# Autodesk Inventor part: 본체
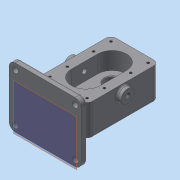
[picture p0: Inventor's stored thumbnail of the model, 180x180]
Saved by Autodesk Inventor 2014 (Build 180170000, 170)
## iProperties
Created: 2026-10
Part Number: 본체
Material: 일반
Document SubType Name: Modeling
Designer: dg
Density: 1 g/cm^3
Appearance: 기본값
Author: dg
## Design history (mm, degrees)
sketch "스케치1"
  geometry: L1 (-40, 60)-(40, 60); L2 (40, 60)-(40, -60); L3 (40, -60)-(-40, -60); L4 (-40, -60)-(-40, 60); 3 further points
  constraints: 8 end point, 2 midpoint, 2 parallel, 1 horizontal, 1 horizontal alignment, 1 perpendicular, 1 vertical alignment
  dimensions: "d0" = 80 distance of L1.start L1.end; "d1" = 120 distance of L3.end L1.start
extrude "돌출1" new body sketch "스케치1" stored distance "d2" = 53; taper "d3" = 0 deg
sketch "스케치2"
  geometry: L1 (-40, 60)-(-40, -60) reference; L2 (0, 22)-(0, -22); L3 (-24, 22)-(-24, -22); L4 (24, -22)-(24, 22); A1 r 24 centre (0, 22) between (24, 22) and (-24, 22); A2 r 24 centre (0, -22) between (-24, -22) and (24, -22); 2 further points
  constraints: 8 end point, 4 point on circle, 4 tangent, 2 centre point, 2 coincident, 2 parallel, 1 midpoint
  dimensions: "d4" = 44 distance of L2.end L2.start; "d6" = 48 distance between parallel lines of L4 L3
extrude "돌출2" cut sketch "스케치2" distance "d7" = 29; taper "d8" = 0 deg
fillet "모깎기1" dims "d9" = 9
sketch "스케치5"
  geometry: C1 r 19 at (0, 22); 1 further point
  constraints: 1 centre point, 1 vertical alignment
  dimensions: "d13" = 22 distance of point (0, 0) C1.centre; "d14" = 38 diameter of C1
extrude "돌출3" join sketch "스케치5" distance "d15" = 17; taper "d16" = 0 deg
sketch "스케치6"
  geometry: L1 (22, -2.623)-(22, -43.5); L2 (3, -43.5)-(41, -43.5) reference; L3 (22, -2.5)-(46, -2.5) reference; L4 (34.5, -2.5)-(34.5, -17.5); L5 (34.5, -17.5)-(30.5, -17.5); L6 (30.5, -17.5)-(30.5, -36.2); L7 (30.5, -36.2)-(36, -36.2); L8 (36, -36.2)-(36, -42.8); L9 (36, -42.8)-(36.404, -43.5); L10 (-22, -2.623)-(-22, -17.5); L11 (-22, -17.5)-(-9.5, -17.5); L12 (-9.5, -17.5)-(-9.5, -2.5); L13 (-22, -2.5)-(22, -2.5) reference; L14 (34.5, -2.5)-(22, -2.5); L15 (36.404, -43.5)-(22, -43.5); L16 (-9.5, -2.5)-(-22, -2.5); L17 (22, -2.5)-(22, -43.5); L18 (-22, -2.5)-(-22, -17.5); 1 further point
  constraints: 30 end point, 5 parallel, 3 collinear, 3 point on line, 2 perpendicular, 1 horizontal, 1 midpoint, 1 vertical
  dimensions: "d17" = 22 distance from line of point (0, 0) L1; "d18" = 7.3 distance from line of L9.end L7; "d19" = 30 deg angle of L8 L9; "d20" = 15 distance of L4.start L4.end; "d21" = 25 diameter of L4 L1; "d22" = 17 diameter of L6 L1; "d25" = 0.7 vertical distance of L8.end L9.end; "d26" = 22 distance from line of L10 point (0, 0); "d27" = 25 diameter of L12 L10; "d28" = 15 distance of L11.end L12.end; "d115" = 28 diameter of L8 L1
revolve "회전1" stored, may be unused: angle "d29" = 90 deg
revolve "회전2" stored, may be unused: angle "d30" = 90 deg
node "작업 평면1"
sketch "스케치7"
  geometry: L1 (-60, 56.5)-(60, 56.5); L2 (60, 56.5)-(60, -43.5); L3 (-60, -43.5)-(-60, 56.5); L4 (-19, -43.5)-(19, -43.5) reference; L5 (-60, -43.5)-(60, -43.5); 3 further points
  constraints: 8 end point, 3 midpoint, 2 parallel, 1 collinear, 1 horizontal, 1 perpendicular, 1 vertical alignment
  dimensions: "d34" = 100 distance of L3.start L1.start; "d35" = 120 distance between parallel lines of L2 L3
extrude "돌출4" join sketch "스케치7" distance "d36" = 10; taper "d37" = 0 deg
sketch "스케치8"
  geometry: L1 (-80, -43.5)-(-80, 56.5) reference; L2 (-80, 26.5)-(-46, 6.87); L3 (-46, -6.87)-(-80, -26.5); L4 (-46, 6.87)-(-46, -6.87); L5 (-46, 26.5)-(-46, -2.5) reference; 2 further points
  constraints: 6 end point, 3 point on line, 1 midpoint, 1 parallel
  dimensions: "d38" = 17 distance of L1.start L3.end; "d39" = 53 distance of L3.end L2.start; "d40" = 60 deg angle of L1 L2; "d41" = 60 deg angle of L1 L3
extrude "돌출5" join sketch "스케치8" stored distance "d42" = 48; taper "d43" = 0 deg
fillet "모깎기2" dims "d49" = 10
sketch "스케치10"
  geometry: A1 r 9 centre (31, 51) between (40, 51) and (31, 60) reference; A2 r 9 centre (-31, 51) between (-31, 60) and (-40, 51) reference; 5 further points
  constraints: 2 coincident, 2 vertical alignment, 1 horizontal alignment
  dimensions: "d50" = 29 distance of point (-31, 22) point (-31, 51)
hole "구멍1" sketch "스케치10" at (-31, 51), (-31, 22), (31, 51), (31, 22) diameter "d51" = 4.134; stored, may be unused: countersink angle "d55" = 82 deg, drill point angle "d57" = 118 deg; dims "d52" = 10, "d53" = 3.023, "d54" = 2, "d56" = 12
node "작업 평면2"
sketch "스케치11"
  geometry: L1 (-40, 51)-(-40, -51) reference; L2 (40, -51)-(40, 51) reference; L3 (-40, 0)-(-48, 0); L4 (40, 0)-(48, 0); L5 (-48, 0)-(-48, 11); L6 (-48, 11)-(-40, 11); L7 (48, 0)-(48, 11); L8 (48, 11)-(40, 11); 1 further point
  constraints: 12 end point, 5 perpendicular, 2 midpoint, 2 point on line, 1 collinear, 1 horizontal alignment
  dimensions: "d59" = 22 diameter of L6 L3; "d60" = 48 distance from line of point (0, 0) L5; "d61" = 96 distance between parallel lines of L7 L5
revolve "회전4" sketch "스케치11" stored, may be unused: angle "d62" = 90 deg
hole "구멍2" diameter "d65" = 8; stored, may be unused: countersink angle "d71" = 90 deg, drill point angle "d73" = 0 deg; dims "d63" = 10, "d64" = 10, "d66" = 9, "d67" = 0.62479, "d68" = 7.985, "d69" = 4, "d70" = 2, "d72" = 8
hole "구멍3" diameter "d76" = 8; stored, may be unused: countersink angle "d82" = 90 deg, drill point angle "d84" = 0 deg; dims "d74" = 10, "d75" = 10, "d77" = 9, "d78" = 0.62479, "d79" = 7.985, "d80" = 4, "d81" = 2, "d83" = 8
sketch "스케치13"
  geometry: L1 (-60, 33.5)-(-60, -46.5) reference; L2 (-50, -56.5)-(50, -56.5) reference; L3 (50, 43.5)-(-50, 43.5) reference; L4 (31, 26.5)-(31, -26.5) reference; L5 (-31, 26.5)-(31, 26.5) reference; L6 (-31, -26.5)-(-31, 26.5) reference; L7 (31, -26.5)-(-31, -26.5) reference; C1 r 5 at (-50, -46.5); C2 r 5 at (50, -46.5); C3 r 5 at (-50, 33.5); C4 r 5 at (50, 33.5); A1 r 10 centre (-50, -46.5) between (-60, -46.5) and (-50, -56.5) reference; 1 further point
  constraints: 4 centre point, 3 equal radius, 2 horizontal alignment, 2 vertical alignment
  dimensions: "d88" = 10 diameter of C3; "d89" = 10 distance from line of L3 C3.centre; "d90" = 10 distance from line of L2 C1.centre; "d94" = 10 distance from line of L1 C1.centre; "d95" = 100 distance of C2.centre A1.centre
extrude "돌출6" cut sketch "스케치13" stored distance "d96" = 10; taper "d97" = 0 deg
fillet "모깎기3" dims "d98" = 3
fillet "모깎기4" dims "d99" = 3
fillet "모깎기5" dims "d100" = 3
fillet "모깎기6" dims "d101" = 3
fillet "모깎기7" dims "d102" = 3
fillet "모깎기8" dims "d103" = 3
fillet "모깎기9" dims "d104" = 3
chamfer "모따기1" distance "d105" = 1; stored, may be unused: second distance "d106" = 2, angle "d107" = 45 deg
chamfer "모따기2" distance "d108" = 1; stored, may be unused: second distance "d109" = 2, angle "d110" = 45 deg
fillet "모깎기10" dims "d111" = 0.5
sketch "스케치14"
  geometry: L1 (-50, -56.5)-(50, -56.5) reference; 2 further points
  constraints: 1 vertical alignment, 1 other
  dimensions: "d112" = 10 distance from line of L1 point (0, -46.5)
feature "엠보싱1" sketch "스케치14" dims "d113" = 0.4, "d114" = 0
sketch "스케치15"
  geometry: 1 further point
node "솔리드1"
mirror "대칭1"
node "투영된 루프1"
other parameters: "d58" = 12.5
